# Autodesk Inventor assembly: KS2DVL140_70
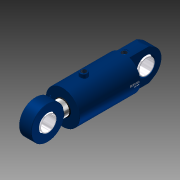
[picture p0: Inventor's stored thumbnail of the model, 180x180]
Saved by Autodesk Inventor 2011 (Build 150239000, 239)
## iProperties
Created: 2010-11
Document SubType Name: Assembly
Designer: TB
Mass: 566.294 g
Surface Area: 1153.75 cm^2
Volume: 566.294 cm^3
Density: 1 g/cm^3
Description: KS2DVL 140/70 - 100 mm
Slaglengde: 100,000 mm
Author: TB
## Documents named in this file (6)
- C:\Vault\Sylinderteknikk\Projects_ST\3D.nettkatalog\KS2-Series\KS2DVL\KS2DVL140_70\KS2DVL140_70.iam
- C:\Vault\Sylinderteknikk\Projects_ST\3D.nettkatalog\KS2-Series\KS2DVL\KS2DVL140_70\KS2DVL140_70_stang.ipt
- C:\Vault\Sylinderteknikk\Projects_ST\3D.nettkatalog\KS2-Series\KS2DVL\KS2DVL140_70\KS2DVL140_70_Parameters.ipt
- C:\Vault\Sylinderteknikk\Projects_ST\3D.nettkatalog\KS2-Series\KS2DVL\KS2DVL140_70\KS2DVL140_70_body..ipt
- C:\Vault\Sylinderteknikk\Projects_ST\Øyer\Klinkby.KS.Øyer\KS.70.eye.komplett\KS.70.eye.komplett.ipt
- C:\Vault\Sylinderteknikk\Projects_ST\Øyer\Klinkby.KS.Øyer\KS.70.eye.komplett\Kule70HO.ipt
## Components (5 placed, 5 different names)
1. KS2DVL140_70_Parameters:3
2. KS2DVL140_70_stang:1 — Mate:1, FriMate:2, Mate:3, Insert:1
3. KS2DVL140_70_body.:1 — Mate:1, FriMate:2, Mate:3, Angle:1, Insert:2
4. KS.70.eye.komplett:1 — Insert:1, Angle:1
5. Kule70HO:1 — Insert:2
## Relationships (6: Mate 3, Insert 2, Angle 1)
- Mate:1: KS2DVL140_70_stang:1 ↔ KS2DVL140_70_body.:1
- FriMate:2 [Mate]: KS2DVL140_70_stang:1 ↔ KS2DVL140_70_body.:1
- Mate:3: KS2DVL140_70_stang:1 ↔ KS2DVL140_70_body.:1
- Insert:1: KS2DVL140_70_stang:1 ↔ KS.70.eye.komplett:1
- Angle:1: KS2DVL140_70_body.:1 ↔ KS.70.eye.komplett:1
- Insert:2: KS2DVL140_70_body.:1 ↔ Kule70HO:1
## Named parameters: Forlengelse_rør = 0, Vinkel_Minusport = 0
